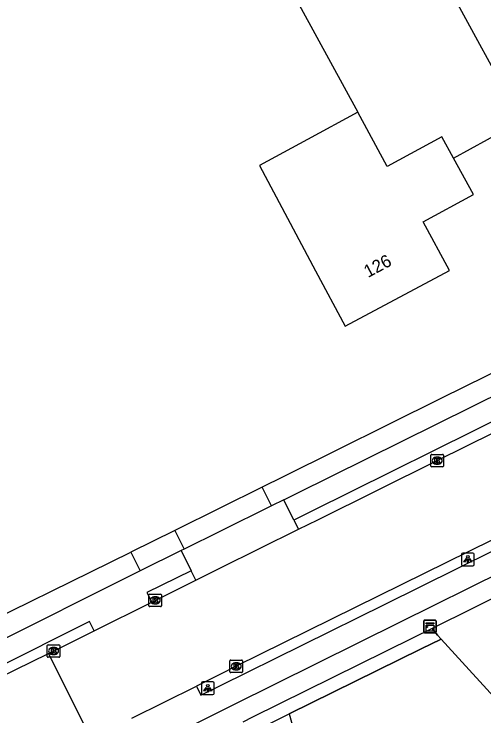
# Model space of a CAD drawing. Extents: x 157321 to 158827, y 386650 to 388532.
# Drawn here: x 157483.6 to 157520.9, y 387596.5 to 387652.3 of the extents above; entities that cross this region are included whole.
import ezdxf

# ---------------------------------------------------------------- set-up
doc = ezdxf.new("R2010")
doc.units = 0
for name, color, linetype in [('IMGEO_Fietspad_open', 7, 'Continuous'), ('IMGEO_Groenvoorziening', 7, 'Continuous'), ('IMGEO_Haag', 7, 'Continuous'), ('IMGEO_Hek', 7, 'Continuous'), ('IMGEO_Kast', 7, 'Continuous'), ('IMGEO_Kolk', 7, 'Continuous'), ('IMGEO_Lichtpunt', 7, 'Continuous'), ('IMGEO_Pand', 7, 'Continuous'), ('IMGEO_Pand_nummerreeks', 7, 'Continuous'), ('IMGEO_Rijbaan_lokaal_open', 7, 'Continuous'), ('IMGEO_Voetpad_open', 7, 'Continuous')]:
    doc.layers.add(name, color=color, linetype=linetype)

msp = doc.modelspace()

# ---------------------------------------------------------------- linework, layer by layer
at = {"layer": 'IMGEO_Fietspad_open'}
for points in [[(157505.035, 387613.71), (157506.043, 387614.209), (157522.765, 387622.48), (157536.678, 387629.402), (157553.691, 387637.874)], [(157555.083, 387636.479), (157533.2, 387625.612), (157523.314, 387620.754), (157507.194, 387612.771), (157505.833, 387612.097)], [(157498.085, 387598.904), (157498.446, 387598.178), (157500, 387598.947), (157513.079, 387605.421), (157521.688, 387609.683), (157550.724, 387624.167), (157560.959, 387629.234)], [(157486.565, 387590.235), (157500, 387596.925), (157501.066, 387597.456), (157514.23, 387603.984), (157522.473, 387608.072), (157552.115, 387622.822), (157562.729, 387628.115)], [(157496.875, 387609.683), (157493.609, 387608.049)], [(157493.609, 387608.049), (157481.236, 387601.856)], [(157497.671, 387608.063), (157494.158, 387606.329), (157494.546, 387605.58)], [(157489.962, 387603.288), (157489.602, 387604.03), (157482.017, 387600.249)]]:
    msp.add_lwpolyline(points, dxfattribs=at)
at = {"layer": 'IMGEO_Groenvoorziening'}
msp.add_lwpolyline([(157517.52, 387602.638), (157562.957, 387552.907), (157563.938, 387551.687)], dxfattribs=at)
at = {"layer": 'IMGEO_Haag'}
for points in [[(157516.796, 387603.48), (157517.241, 387602.962), (157517.52, 387602.638)], [(157517.52, 387602.638), (157515.932, 387601.859), (157505.447, 387596.715)]]:
    msp.add_lwpolyline(points, dxfattribs=at)
at = {"layer": 'IMGEO_Hek'}
for points in [[(157517.52, 387602.638), (157517.241, 387602.962), (157516.796, 387603.48)], [(157515.932, 387601.859), (157517.52, 387602.638)], [(157505.447, 387596.715), (157515.932, 387601.859)]]:
    msp.add_lwpolyline(points, dxfattribs=at)
at = {"layer": 'IMGEO_Kast'}
for p, q in [((157516.133, 387603.218), (157516.133, 387604.059)), ((157516.133, 387604.059), (157516.133, 387603.218)), ((157516.208, 387604.143), (157517.049, 387604.143)), ((157517.049, 387604.143), (157516.208, 387604.143)), ((157517.133, 387604.068), (157517.133, 387603.227)), ((157517.133, 387603.227), (157517.133, 387604.068)), ((157517.058, 387603.143), (157516.217, 387603.143)), ((157516.217, 387603.143), (157517.058, 387603.143))]:
    msp.add_line(p, q, dxfattribs=at)
for points in [[(157516.328, 387603.933), (157516.928, 387603.933), (157516.928, 387603.848), (157516.328, 387603.848), (157516.328, 387603.933)], [(157516.328, 387603.758), (157516.928, 387603.758), (157516.928, 387603.269), (157516.328, 387603.269), (157516.328, 387603.758)]]:
    msp.add_lwpolyline(points, dxfattribs=at)
msp.add_circle((157516.412, 387603.607), 0.0377, dxfattribs=at)
for centre, start, end in [((157516.211, 387604.065), 92.4484, 184.2845), ((157516.211, 387604.065), 92.4484, 184.2845), ((157517.055, 387604.065), 2.4484, 94.2845), ((157517.055, 387604.065), 2.4484, 94.2845), ((157516.211, 387603.221), 182.4484, 274.2845), ((157516.211, 387603.221), 182.4484, 274.2845), ((157517.055, 387603.221), 272.4484, 4.2845), ((157517.055, 387603.221), 272.4484, 4.2845)]:
    msp.add_arc(centre, 0.0779, start, end, dxfattribs=at)
at = {"layer": 'IMGEO_Kolk'}
for p, q in [((157516.709, 387616.385), (157516.709, 387617.237)), ((157516.784, 387617.311), (157517.636, 387617.311)), ((157517.197, 387617.091), (157517.222, 387617.091)), ((157517.71, 387617.237), (157517.71, 387616.385)), ((157517.22, 387616.531), (157517.195, 387616.531)), ((157517.636, 387616.311), (157516.784, 387616.311)), ((157494.318, 387605.29), (157494.318, 387606.142)), ((157494.393, 387606.216), (157495.245, 387606.216)), ((157494.806, 387605.996), (157494.831, 387605.996)), ((157495.319, 387606.142), (157495.319, 387605.29)), ((157494.829, 387605.436), (157494.804, 387605.436)), ((157495.245, 387605.216), (157494.393, 387605.216)), ((157486.245, 387601.267), (157486.245, 387602.119)), ((157486.32, 387602.193), (157487.172, 387602.193)), ((157486.733, 387601.973), (157486.758, 387601.973)), ((157487.246, 387602.119), (157487.246, 387601.267)), ((157486.756, 387601.413), (157486.731, 387601.413)), ((157487.172, 387601.193), (157486.32, 387601.193)), ((157500.75, 387600.052), (157500.75, 387600.904)), ((157500.825, 387600.978), (157501.677, 387600.978)), ((157501.751, 387600.904), (157501.751, 387600.052)), ((157501.238, 387600.758), (157501.263, 387600.758)), ((157501.677, 387599.978), (157500.825, 387599.978)), ((157501.261, 387600.198), (157501.236, 387600.198))]:
    msp.add_line(p, q, dxfattribs=at)
for points in [[(157516.709, 387616.385), (157516.709, 387617.237)], [(157516.784, 387617.311), (157517.636, 387617.311)], [(157517.03, 387617.011), (157517.153, 387617.011), (157517.153, 387616.86), (157517.283, 387617.011), (157517.447, 387617.011), (157517.301, 387616.86), (157517.454, 387616.611), (157517.302, 387616.611), (157517.217, 387616.775), (157517.153, 387616.708), (157517.153, 387616.611), (157517.03, 387616.611), (157517.03, 387617.011)], [(157517.71, 387617.237), (157517.71, 387616.385)], [(157517.636, 387616.311), (157516.784, 387616.311)], [(157494.318, 387605.29), (157494.318, 387606.142)], [(157494.393, 387606.216), (157495.245, 387606.216)], [(157494.639, 387605.916), (157494.762, 387605.916), (157494.762, 387605.765), (157494.892, 387605.916), (157495.056, 387605.916), (157494.91, 387605.765), (157495.063, 387605.516), (157494.911, 387605.516), (157494.826, 387605.68), (157494.762, 387605.613), (157494.762, 387605.516), (157494.639, 387605.516), (157494.639, 387605.916)], [(157495.319, 387606.142), (157495.319, 387605.29)], [(157495.245, 387605.216), (157494.393, 387605.216)], [(157486.245, 387601.267), (157486.245, 387602.119)], [(157486.32, 387602.193), (157487.172, 387602.193)], [(157487.246, 387602.119), (157487.246, 387601.267)], [(157486.566, 387601.893), (157486.689, 387601.893), (157486.689, 387601.742), (157486.819, 387601.893), (157486.983, 387601.893), (157486.837, 387601.742), (157486.99, 387601.493), (157486.838, 387601.493), (157486.753, 387601.657), (157486.689, 387601.59), (157486.689, 387601.493), (157486.566, 387601.493), (157486.566, 387601.893)], [(157487.172, 387601.193), (157486.32, 387601.193)], [(157500.75, 387600.052), (157500.75, 387600.904)], [(157500.825, 387600.978), (157501.677, 387600.978)], [(157501.751, 387600.904), (157501.751, 387600.052)], [(157501.071, 387600.678), (157501.194, 387600.678), (157501.194, 387600.527), (157501.324, 387600.678), (157501.488, 387600.678), (157501.342, 387600.527), (157501.495, 387600.278), (157501.343, 387600.278), (157501.258, 387600.442), (157501.194, 387600.375), (157501.194, 387600.278), (157501.071, 387600.278), (157501.071, 387600.678)], [(157501.677, 387599.978), (157500.825, 387599.978)]]:
    msp.add_lwpolyline(points, dxfattribs=at)
for centre, start, end in [((157516.786, 387617.235), 91.552, 178.448), ((157516.786, 387617.235), 91.552, 178.448), ((157517.634, 387617.235), 1.552, 88.448), ((157517.634, 387617.235), 1.552, 88.448), ((157516.786, 387616.387), 181.552, 268.448), ((157516.786, 387616.387), 181.552, 268.448), ((157517.634, 387616.387), 271.552, 358.448), ((157517.634, 387616.387), 271.552, 358.448), ((157494.395, 387606.14), 91.552, 178.448), ((157494.395, 387606.14), 91.552, 178.448), ((157495.243, 387606.14), 1.552, 88.448), ((157495.243, 387606.14), 1.552, 88.448), ((157494.395, 387605.292), 181.552, 268.448), ((157494.395, 387605.292), 181.552, 268.448), ((157495.243, 387605.292), 271.552, 358.448), ((157495.243, 387605.292), 271.552, 358.448), ((157486.322, 387602.117), 91.552, 178.448), ((157486.322, 387602.117), 91.552, 178.448), ((157487.17, 387602.117), 1.552, 88.448), ((157487.17, 387602.117), 1.552, 88.448), ((157486.322, 387601.269), 181.552, 268.448), ((157486.322, 387601.269), 181.552, 268.448), ((157487.17, 387601.269), 271.552, 358.448), ((157487.17, 387601.269), 271.552, 358.448), ((157500.827, 387600.902), 91.552, 178.448), ((157500.827, 387600.902), 91.552, 178.448), ((157501.675, 387600.902), 1.552, 88.448), ((157501.675, 387600.902), 1.552, 88.448), ((157500.827, 387600.054), 181.552, 268.448), ((157500.827, 387600.054), 181.552, 268.448), ((157501.675, 387600.054), 271.552, 358.448), ((157501.675, 387600.054), 271.552, 358.448)]:
    msp.add_arc(centre, 0.0765, start, end, dxfattribs=at)
for centre, major_axis, ratio, start_param, end_param in [((157517.196, 387616.811), (-0.387, 0.002), 0.722429, 4.712389, 7.853982), ((157517.221, 387616.811), (-0.39, 0.002), 0.717154, 1.570796, 4.712389), ((157494.805, 387605.716), (-0.387, 0.002), 0.722429, 4.712389, 7.853982), ((157494.83, 387605.716), (-0.39, 0.002), 0.717154, 1.570796, 4.712389), ((157486.732, 387601.693), (-0.387, 0.002), 0.722429, 4.712389, 7.853982), ((157486.757, 387601.693), (-0.39, 0.002), 0.717154, 1.570796, 4.712389), ((157501.237, 387600.478), (-0.387, 0.002), 0.722429, 4.712389, 7.853982), ((157501.262, 387600.478), (-0.39, 0.002), 0.717154, 1.570796, 4.712389)]:
    msp.add_ellipse(centre, major_axis=major_axis, ratio=ratio, start_param=start_param, end_param=end_param, dxfattribs=at)
at = {"layer": 'IMGEO_Lichtpunt'}
for p, q in [((157519.147, 387609.371), (157519.147, 387608.564)), ((157519.147, 387609.371), (157519.147, 387608.564)), ((157520.049, 387609.466), (157519.241, 387609.466)), ((157520.049, 387609.466), (157519.241, 387609.466)), ((157520.143, 387608.564), (157520.143, 387609.371)), ((157520.143, 387608.564), (157520.143, 387609.371)), ((157519.241, 387608.47), (157520.049, 387608.47)), ((157519.241, 387608.47), (157520.049, 387608.47)), ((157499.393, 387599.235), (157498.585, 387599.235)), ((157499.393, 387599.235), (157498.585, 387599.235)), ((157498.491, 387599.14), (157498.491, 387598.333)), ((157498.491, 387599.14), (157498.491, 387598.333)), ((157499.487, 387598.333), (157499.487, 387599.14)), ((157499.487, 387598.333), (157499.487, 387599.14)), ((157498.585, 387598.239), (157499.393, 387598.239)), ((157498.585, 387598.239), (157499.393, 387598.239))]:
    msp.add_line(p, q, dxfattribs=at)
for points in [[(157519.521, 387609.035), (157519.56, 387609.007), (157519.372, 387608.745), (157519.334, 387608.772), (157519.521, 387609.035)], [(157519.623, 387608.987), (157519.67, 387608.987), (157519.67, 387608.665), (157519.623, 387608.665), (157519.623, 387608.987)], [(157519.733, 387609.007), (157519.771, 387609.034), (157519.958, 387608.772), (157519.919, 387608.744), (157519.733, 387609.007)], [(157498.865, 387598.804), (157498.904, 387598.776), (157498.716, 387598.514), (157498.678, 387598.541), (157498.865, 387598.804)], [(157498.967, 387598.756), (157499.014, 387598.756), (157499.014, 387598.434), (157498.967, 387598.434), (157498.967, 387598.756)], [(157499.077, 387598.776), (157499.115, 387598.803), (157499.302, 387598.541), (157499.263, 387598.513), (157499.077, 387598.776)]]:
    msp.add_lwpolyline(points, dxfattribs=at)
for centre in [(157519.646, 387609.169), (157498.99, 387598.938)]:
    msp.add_circle(centre, 0.0994, dxfattribs=at)
for centre, start, end in [((157519.241, 387609.371), 90, 180), ((157519.241, 387609.371), 90, 180), ((157520.049, 387609.371), 0, 90), ((157520.049, 387609.371), 0, 90), ((157519.241, 387608.564), 180, 270), ((157519.241, 387608.564), 180, 270), ((157520.049, 387608.564), 270, 0), ((157520.049, 387608.564), 270, 360), ((157498.585, 387599.14), 90, 180), ((157498.585, 387599.14), 90, 180), ((157499.393, 387599.14), 0, 90), ((157499.393, 387599.14), 0, 90), ((157498.585, 387598.333), 180, 270), ((157498.585, 387598.333), 180, 270), ((157499.393, 387598.333), 270, 0), ((157499.393, 387598.333), 270, 360)]:
    msp.add_arc(centre, 0.0946, start, end, dxfattribs=at)
at = {"layer": 'IMGEO_Pand'}
for points in [[(157518.506, 387640.838), (157523.911, 387643.783), (157511.895, 387665.837), (157513.847, 387666.901), (157511.931, 387670.416), (157510.119, 387669.428), (157508.788, 387671.869), (157507.453, 387674.317), (157500, 387687.912), (157476.248, 387731.503), (157469.16, 387744.511)], [(157449.469, 387733.793), (157456.747, 387720.365), (157475.612, 387685.559), (157480.905, 387688.442), (157499.583, 387654.162), (157500, 387654.389), (157504.239, 387656.699), (157510.892, 387644.49)], [(157510.892, 387644.49), (157506.896, 387642.314), (157503.092, 387640.242), (157507.54, 387631.892), (157509.891, 387627.479), (157518.182, 387631.91), (157516.082, 387635.765), (157520.082, 387637.945), (157518.506, 387640.838)], [(157518.506, 387640.838), (157517.584, 387642.531), (157513.247, 387640.168), (157510.892, 387644.49)]]:
    msp.add_lwpolyline(points, dxfattribs=at)
at = {"layer": 'IMGEO_Rijbaan_lokaal_open'}
for points in [[(157506.187, 387611.363), (157507.717, 387612.119), (157517.211, 387616.81), (157521.759, 387619.08), (157523.243, 387619.86)], [(157529.042, 387614.221), (157521.536, 387610.5), (157512.562, 387606.067), (157501.251, 387600.479), (157500, 387599.852), (157498.085, 387598.904)], [(157505.035, 387613.71), (157504.06, 387613.232)], [(157505.833, 387612.097), (157505.035, 387613.71)], [(157504.06, 387613.232), (157500, 387611.217), (157497.108, 387609.782)], [(157505.833, 387612.097), (157506.187, 387611.363)], [(157498.034, 387607.324), (157500, 387608.298), (157506.187, 387611.363)], [(157497.108, 387609.782), (157496.875, 387609.683)], [(157496.875, 387609.683), (157497.671, 387608.063)], [(157498.034, 387607.324), (157497.671, 387608.063)], [(157494.546, 387605.58), (157498.034, 387607.324)], [(157489.962, 387603.288), (157494.546, 387605.58)], [(157486.348, 387601.503), (157486.746, 387601.692), (157489.962, 387603.288)], [(157482.357, 387599.577), (157486.348, 387601.503)], [(157489.715, 387594.756), (157486.348, 387601.503)], [(157492.946, 387596.358), (157498.085, 387598.904)]]:
    msp.add_lwpolyline(points, dxfattribs=at)
at = {"layer": 'IMGEO_Voetpad_open'}
for points in [[(157553.174, 387639.447), (157535.44, 387630.592), (157517.556, 387621.762), (157504.981, 387615.535), (157503.32, 387614.713)], [(157560.875, 387625.389), (157552.086, 387621.025), (157523.261, 387606.675), (157516.796, 387603.48)], [(157503.32, 387614.713), (157500, 387613.07), (157496.375, 387611.276)], [(157504.06, 387613.232), (157503.32, 387614.713)], [(157496.375, 387611.276), (157492.871, 387609.553)], [(157496.375, 387611.276), (157497.108, 387609.782)], [(157475.55, 387600.981), (157478.632, 387602.553), (157492.871, 387609.553)], [(157492.871, 387609.553), (157493.609, 387608.049)], [(157516.796, 387603.48), (157515.247, 387602.714), (157502.531, 387596.428), (157501.782, 387596.049)], [(157501.241, 387593.925), (157501.657, 387592.501), (157502.624, 387592.787), (157502.03, 387595.002), (157505.447, 387596.715)], [(157505.447, 387596.715), (157507.682, 387588.774), (157504.068, 387587.703)]]:
    msp.add_lwpolyline(points, dxfattribs=at)

# ---------------------------------------------------------------- texts
at = {"layer": 'IMGEO_Pand_nummerreeks'}
msp.add_text('126', height=1, rotation=28.1208, dxfattribs=at).set_placement((157511.714, 387631.31))

doc.saveas('drawing.dxf')
